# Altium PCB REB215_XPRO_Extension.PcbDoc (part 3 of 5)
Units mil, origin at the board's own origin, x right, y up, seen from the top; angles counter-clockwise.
Board outline 4055.74 x 2606 mil, 6 copper layers (Top Layer LF-signals, Signal Layer 1, Internal Plane 1, Mid-1, Mid-2, Bottom Layer LF-signals), stack 58.434 mil thick; 278 components, 292 nets, 1282 pads, 1177 vias.
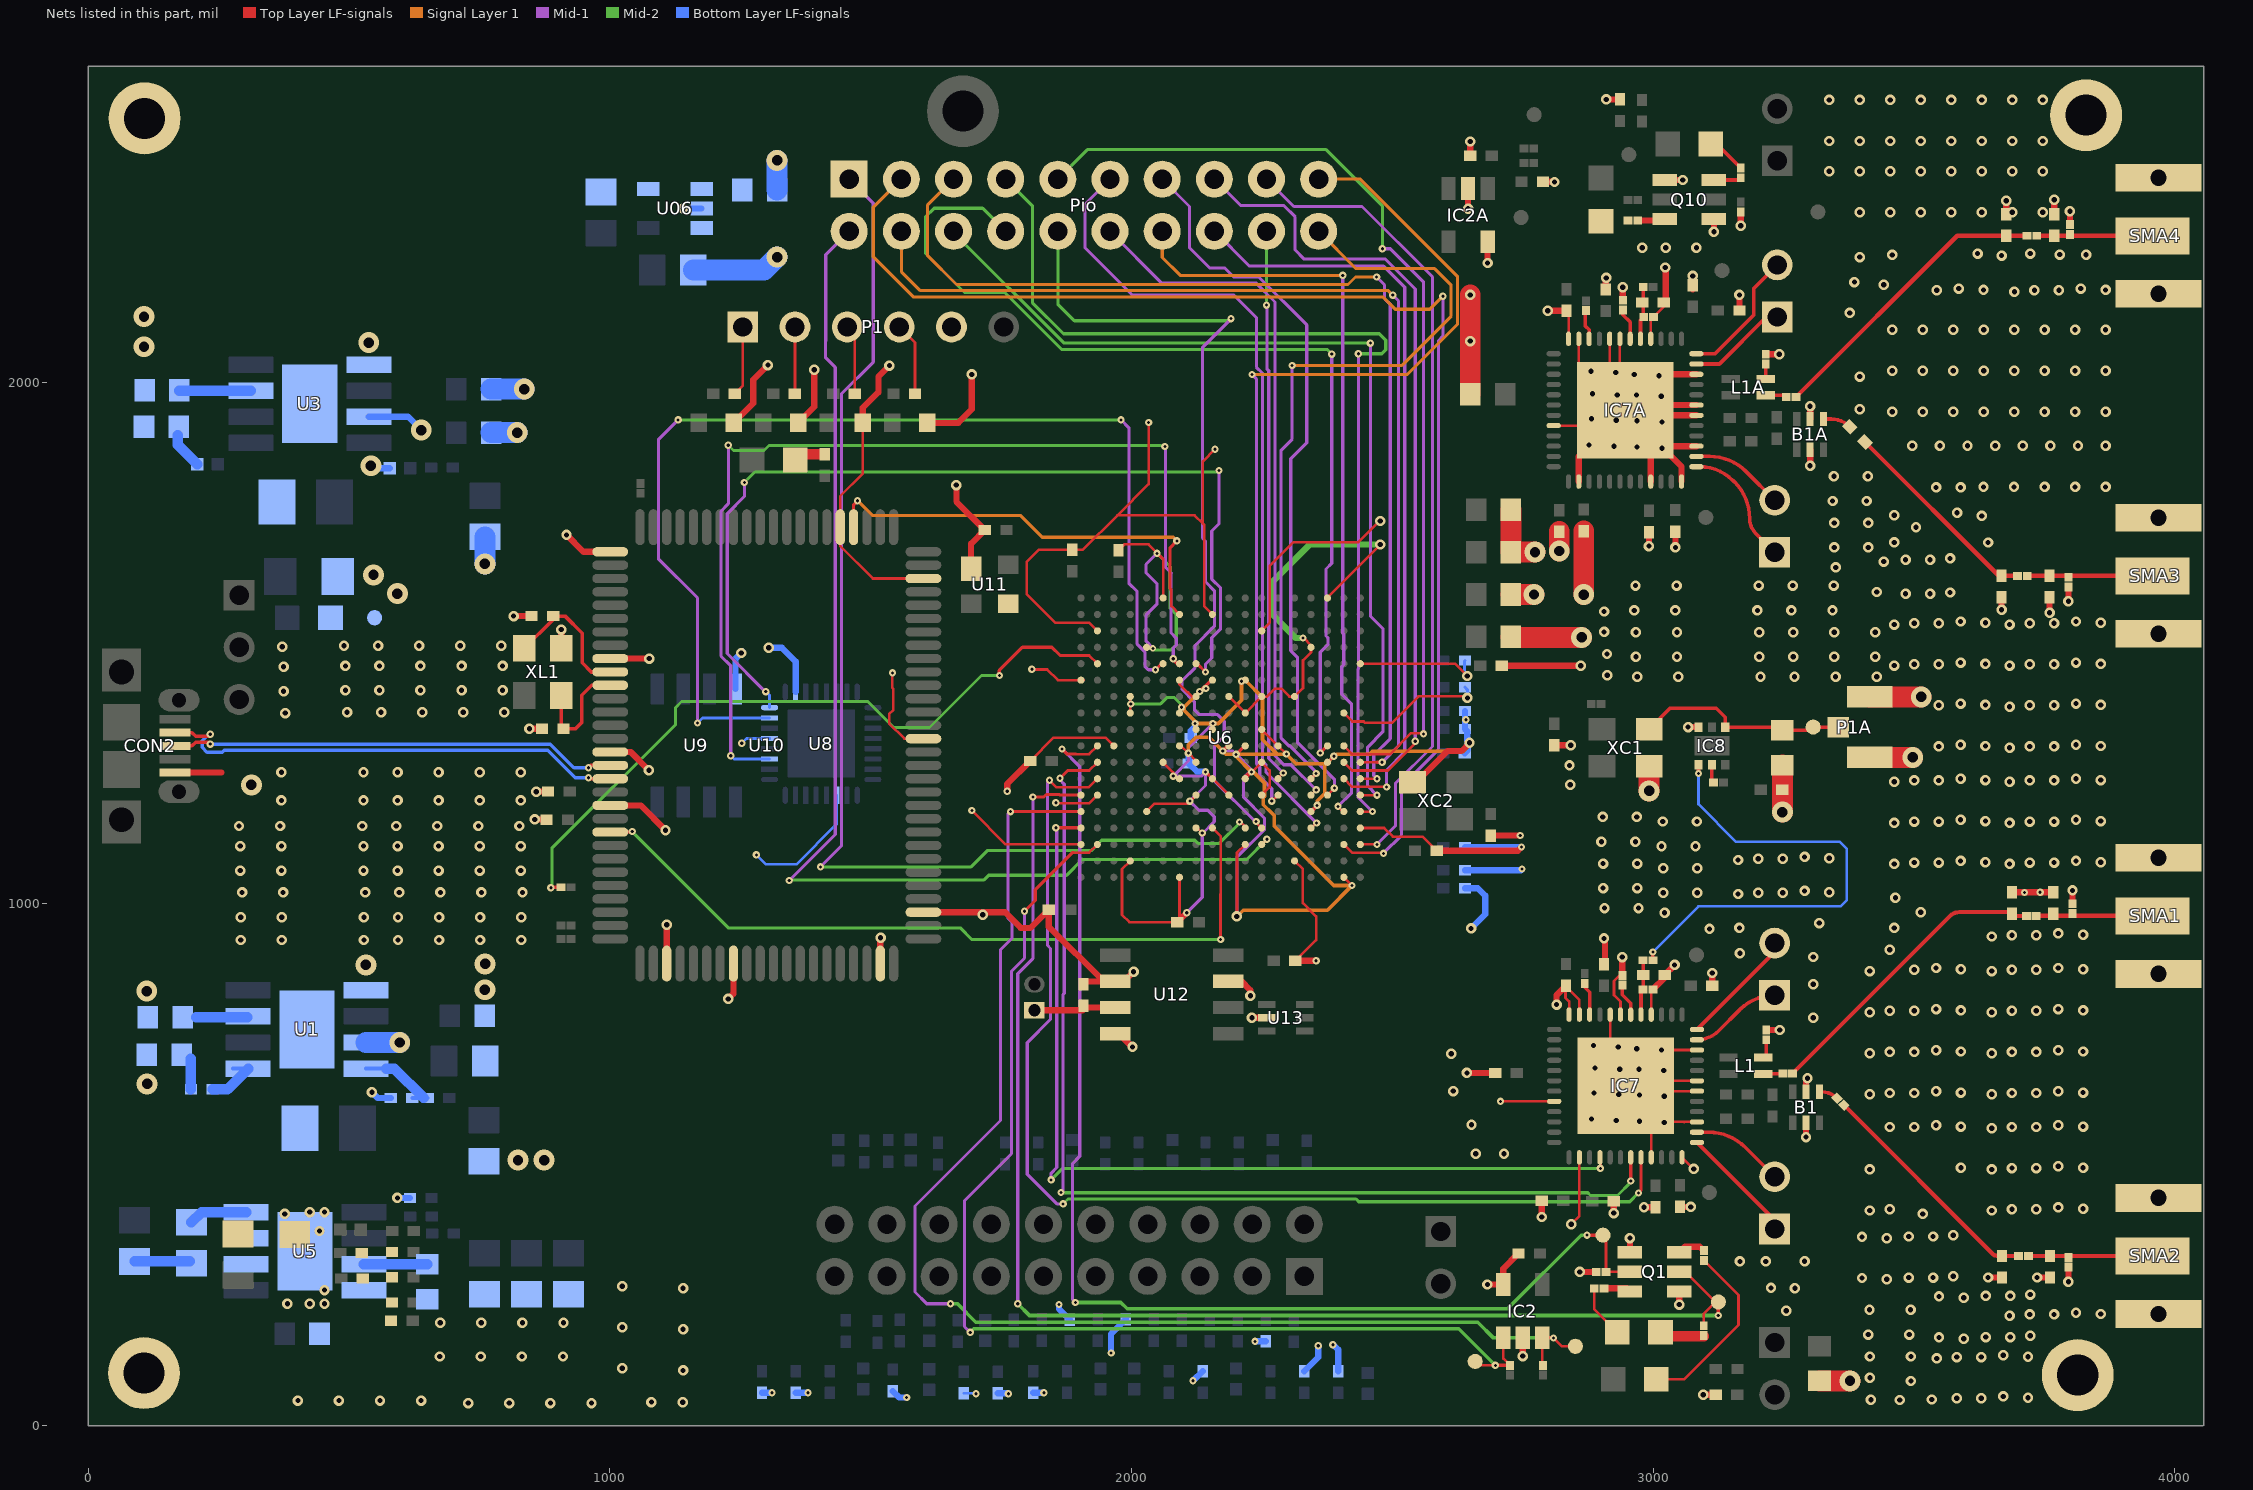
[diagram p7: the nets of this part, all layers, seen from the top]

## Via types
v1: diameter 20, hole 10, Top Layer LF-signals to Bottom Layer LF-signals, 660 vias
v2: diameter 14, hole 6, Top Layer LF-signals to Bottom Layer LF-signals, 470 vias
v3: diameter 40, hole 20, Top Layer LF-signals to Bottom Layer LF-signals, 46 vias
v4: diameter 12, hole 6, Top Layer LF-signals to Bottom Layer LF-signals, 1 vias

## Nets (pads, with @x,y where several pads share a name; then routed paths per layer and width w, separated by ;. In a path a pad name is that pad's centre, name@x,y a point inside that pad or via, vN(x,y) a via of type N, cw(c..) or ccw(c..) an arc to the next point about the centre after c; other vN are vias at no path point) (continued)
GND: B1.2 B1.5 B1A.2 B1A.5 C1.1 C01.2 C001.2 C1A.1 C002.2 C4.2 C4A.2 C5.2 C5A.2 C7.2 C7A.2 C9.2 C10.2 C10A.2 C11.1 C13.2 C13A.2 C14.2 C14A.2 C15.2 C15A.2 C16.2 C16A.2 C17.2 C17A.2 C18.2 C18A.2 C19.2 C19A.2 C20.2 C20A.2 C21.2 C21A.2 C22.2 C22A.2 C23.2 C24.2 C024A.2 C24A.2 C26.2 C27.2 C28.2 C29.2 C30.2 C31.2 C32.2 C33.2 C34.2 C35.2 C43.2 C44.2 C45.2 C46.2 C47.2 C48.2 C49.2 C50.2 C51.2 C52.2 C53.2 C54.2 C55.2 C56.2 C57.2 C58.2 C59.2 C60.2 C61.2 C62.2 C63.2 C64.2 C65.2 C66.2 C67.2 C68.2 C69.2 C70.2 C71.2 C72.2 C73.2 C74.2 C75.2 C76.2 C77.2 C78.2 C79.2 C80.2 C81.2 C82.2 C110.1 C230.2 CON2.5 D001.1 DA.1 DB.1 DC.1 DD.1 IC2.2 IC2.5 IC2A.2 IC2A.5 IC7.3 IC7.6 IC7.7 IC7.10@3084.06,719.91 IC7.16@2996.46,787.82 IC7.19 IC7.20 IC7.23 IC7.24 IC7.32 IC7.38 IC7.45 IC7.48 IC7.49 IC7A.3 IC7A.6 IC7A.7 IC7A.10@3083.06,2015.37 IC7A.16@2995.46,2083.28 IC7A.19 IC7A.20 IC7A.23 IC7A.24 IC7A.32 IC7A.38 IC7A.45 IC7A.48 IC7A.49 IC8.3 P1.5 P1A.2 P1A.3 pad.0 pad.1 pad.3 pad.4 Q1.1 Q1.4 Q10.1 Q10.4 R5.2 R5A.2 R7.2 R7A.2 R10.1 R10A.1 R11.1 R11A.1 R13.1 R13A.1 R16.1 R19.1 R25.2 R032.2 R46.2 R47.2 R48.2 R49.2 R50.2 R51.2 R53.1 R54.1 R55.1 R56.1 R57.1 R58.1 SMA1.2 SMA1.2.1 SMA2.2 SMA2.2.1 SMA3.2 SMA3.2.1 SMA4.2 SMA4.2.1 TP9.1 U1.1 U1.3 U3.1 U3.3 U5.9 U06.2 U6.A2 U6.A12 U6.B5 U6.B15 U6.C8 U6.C18 U6.D1 U6.D11 U6.E4 U6.E14 U6.F7 U6.F9 U6.F11 U6.F17 U6.G8 U6.G10 U6.G12 U6.H3 U6.H7 U6.H11 U6.H13 U6.J6 U6.J8 U6.J9 U6.J12 U6.J16 U6.K7 U6.K10 U6.K11 U6.L2 U6.L8 U6.L12 U6.L15 U6.M5 U6.M7 U6.M9 U6.M11 U6.M15 U6.N8 U6.N10 U6.N12 U6.N18 U6.P1 U6.R4 U6.R14 U6.T7 U6.T17 U6.U10 U6.V3 U6.V13 U8.11 U8.21 U8.26 U9.4 U10.1 U10.9 U10.16 U10.20 U10.33 U10.38 U10.49 U10.53 U10.66 U10.78 U10.85 U11.1 U12.2 U12.4 U12.7 U13.2 XC1.2 XC2.2 XL1.2 | length 19395.7
  Top Layer LF-signals w5: DB.1@1484.99,1922.18 1484.99,1825.03 1441.75,1781.78 U10.85@1441.75,1722.31 1441.75,1686.25 1504.12,1623.88 U10.78@1601.2,1623.88 ; v2(1541.76,1443) 1541.76,1414.15 1543.41,1412.51 1543.41,1371.74 1535.59,1363.93 1535.59,1345.78 1564.58,1316.8 U10.66@1601.2,1316.8 ; U11.1@1689,1646.1 1689,1686.79 1692.57,1690.36 ; v2(1694,1179) 1758.95,1114.05 U6.C18@1903.2,1114.05 ; C73.2@1806,1274 1850.77,1318.77 1950.45,1318.77 U6.J16@1966.19,1303.02 ; v2(1809,1450) 1808.51,1449.49 1838.31,1449.49 1858.79,1429.01 U6.N18@1903.2,1429.01 U6.N18@1908.65,1429.01 ; v2(1855,1194) 1856.21,1192.79 1918.95,1192.79 U6.F17@1934.7,1208.54 ; U6.T17@1934.7,1523.5 1918.95,1539.24 1853.61,1539.24 1799,1593.85 1799,1655.68 1822.32,1679 C74.2@1886.73,1679 1906.91,1679 1972.91,1745 ; U12.2@1946.55,851.45 U12.2@1968.83,851.45 ; C75.2@1975,1687.12 C75.2@1975,1678 1986.41,1689.41 2033.01,1689.41 2060.68,1661.73 2060.68,1660.32 ; U6.B15@1997.69,1082.55 1981.94,1066.8 1981.94,978.94 1995.88,965 C71.2@2088,965 ; U6.L15@1997.69,1366.02 U6.M15@1997.69,1397.51 ; U6.R14@2028.59,1492.59 U6.R14@2029.19,1492 v4@2039,1492 ; U6.E14@2029.19,1177.04 2044.48,1192.34 2107.34,1192.34 v2(2112,1197) 2113,1197 2123.67,1207.67 U6.F11@2123.67,1208.54 ; v2(2032.98,1923) 2032.98,1805.08 1972.91,1745 ; v2@2046.84,1674.16 v2(2049,1672) 2060.68,1660.32 ; U6.H13@2060.68,1271.53 2080,1252.21 v2(2080,1245) ; U6.V13@2060.68,1586.49 2060.68,1660.32 ; C71.2@2092.18,969.18 U6.A12@2092.18,1051.06 ; U6.G12@2092.18,1240.03 U6.G12@2092.18,1242.64 ; U6.J12@2092.18,1303.02 2094.98,1303.02 v2(2109,1289) 2123.67,1274.33 U6.H11@2123.67,1271.53 ; U6.L12@2092.18,1366.02 2093.41,1367.24 v2@2093.41,1380.86 ; U6.N12@2092.18,1429.01 2092.18,1421.04 2107.62,1405.6 2108.41,1405.6 2116.49,1397.51 ; U6.D11@2123.67,1145.54 2126.12,1145.54 v2(2135.66,1136) v2@2139,1132.66 ; 2147,1248.2 U6.G10@2155.17,1240.03 U6.F9@2186.67,1208.54 ; U6.U10@2155.17,1554.99 2139.42,1570.74 2139.42,1726.58 2136.84,1729.16 ; v2(2160,1871.67) 2136.84,1848.51 2136.84,1729.16 ; U6.M9@2186.67,1397.51 U6.L8@2218.16,1366.02 U6.M7@2249.66,1397.51 2259.52,1397.51 2274.82,1412.81 2287.49,1412.81 2302.79,1397.51 U6.M5@2312.65,1397.51 2328.85,1413.71 2328.85,1466.84 2344.15,1482.14 U6.R4@2344.15,1492 2340.79,1492 2344.63,1495.84 2330.68,1509.79 v2(2328.72,1509.79) ; v1(2202,976) 2202.41,976.41 2202.41,1098.3 U6.C8@2218.16,1114.05 ; v2@2210,1422 2217.01,1429.01 U6.N8@2218.16,1429.01 ; v2(2230,1253) 2226,1253 2213.03,1240.03 U6.G8@2218.16,1240.03 U6.H7@2249.66,1271.53 2264.95,1256.23 2264.95,1223.83 U6.F7@2249.66,1208.54 ; U6.K7@2249.66,1334.52 U6.J6@2281.15,1303.02 v2(2296.9,1287.28) ; U6.T7@2249.66,1523.5 2265.41,1539.24 2265.41,1648.5 2309.91,1693 2434.08,1693 2475.15,1734.07 v1(2476.91,1734.07) v1@2476.77,1733.94 ; U6.B5@2312.65,1082.55 2328.4,1066.8 2328.4,1001.6 2353.89,976.11 2353.89,930.89 2314.33,891.33 C68.2@2314,891 ; U6.H3@2375.64,1271.53 2388,1283.89 v2(2388,1283) ; U6.V3@2375.64,1586.49 2375.64,1587.64 v1(2477,1689) ; U6.A2@2407.14,1051.06 v2(2422.89,1035.31) ; U6.L2@2407.14,1366.02 2423.34,1349.82 2444.97,1349.82 2447.78,1347 2499,1347 2550,1398 v1@2641,1398 ; U6.D1@2438.63,1145.54 2484.36,1145.54 2500.9,1129 2558.09,1129 C76.2@2585,1102.1 ; U6.P1@2438.63,1460.5 2620.35,1460.5 v1(2643.91,1436.95) ; v2(2707.48,621.48) IC7.32@2810.43,621.48 ; IC7A.32@2809.43,1916.95 IC7A.49@2916.72,1916.95 ; IC7A.24@2837.98,2083.28 C24A.2@2837.98,2133.01 ; IC7.24@2838.98,787.82 2838.98,813.02 2832,820 2832,842.38 2858.66,815.72 IC7.23@2858.66,787.82 ; v1(2843,386) 2858.66,401.66 IC7.38@2858.66,514.2 ; IC7A.49@2857.66,2035.06 IC7A.23@2857.66,2083.28 ; IC7A.49@2916.72,1976 IC7A.20@2916.72,2083.28 ; IC7.49@2917.72,680.54 IC7.20@2917.72,787.82 ; R7.2@2935.77,863.07 2925.05,852.35 2925.05,825.01 2937.4,812.66 IC7.19@2937.4,787.82 ; IC7A.49@2936.4,1956.32 IC7A.19@2936.4,2083.28 ; IC7.49@2947.24,651.01 IC7.49@2957.09,641.17 ; IC7.49@2957.09,660.85 IC7.7@3084.06,660.85 ; IC7A.16@2995.46,2083.28 2995.46,2119.76 R13A.1@3000.7,2125 C10A.2@3020.34,2144.64 ; IC7.45@2996.46,514.2 2996.46,601.8 IC7.49@2957.09,641.17 ; IC7.16@2996.46,787.82 R13.1@2996.46,832.95 ; IC7.49@3016.14,582.11 3060.11,582.11 ; v1(3016.14,719.91) IC7.10@3084.06,719.91 ; IC7.48@3055.51,514.2 v1(3077.71,492) ; 3060,582 3060.11,582.11 ; IC7.3@3084.06,582.11 3060.11,582.11 ; IC7.6@3084.06,641.17 IC7.49@2957.09,641.17 ; 1972.91,1745 2121,1745 2136.84,1729.16
  Top Layer LF-signals w6: v2@2707,621 v2(2707.48,621.48)
  Top Layer LF-signals w7: U6.M11@2123.67,1397.51 2123.67,1399.85 v2(2131,1407.17) 2152.84,1429.01 U6.N10@2155.17,1429.01 ; v2(2142,1253.2) 2147,1248.2 ; U6.G10@2153.68,1240.03 U6.G10@2155.17,1240.03 ; v2(2175,1293) 2185.02,1303.02 U6.J9@2186.67,1303.02 ; v2(2200.73,1286.81) 2216.95,1303.02 U6.J8@2218.16,1303.02 ; U6.E4@2344.15,1177.04 v2(2356,1188.89)
  Top Layer LF-signals w12: CON2.5@166.24,1251.82 255.61,1251.82 ; v1(815.57,1551.81) C002.2@850,1551.81 ; v1(845.84,1336) C01.2@870,1336 ; v1@857.74,1162 v1(856,1162) 856.37,1161.63 C69.2@878.66,1161.63 ; v1(859,1215) 859.4,1215.4 C67.2@881.66,1215.4 ; XL1.2@906.87,1489.99 906.87,1525.87 v1(907,1526) v1@907,1526.65 ; v1(917,1707.47) 949.41,1675.06 U10.1@1000.8,1675.06 ; U10.20@1000.8,1188.84 1059.16,1188.84 v1(1106.78,1141.22) ; U10.16@1000.8,1291.21 1040.03,1291.21 v1(1075,1256.23) ; U10.9@1000.8,1470.34 v1(1075.66,1470.34) ; U10.33@1109.07,885.69 v1(1109.07,959.93) ; v1(1227,818) 1237.02,828.02 U10.38@1237.02,885.69 ; DD.1@1237.6,1922.18 1275,1959.58 1275,2005 v1(1303,2033) ; DC.1@1361.3,1922.18 1392,1952.88 v1(1392,2024) ; DB.1@1484.99,1922.18 1484.99,1950.99 1515,1981 1515,2011 v1(1536,2032) ; U10.49@1518.52,885.69 1518.52,934.52 v1(1519,935) v1@1519,935.56 ; U10.53@1601.2,984.12 v1@1709.77,984.12 ; DA.1@1608.69,1922.18 1667.82,1922.18 1694,1948.36 v1(1694,2015) ; v1(1664,1803) 1664.47,1802.53 1664.47,1771.32 C65.2@1719,1716.79 1692.57,1690.36 U11.1@1692.57,1642.53 ; v1(1714.81,979.08) v1@1709.77,984.12 ; v2(1762,1216) 1762,1230 C73.2@1806,1274 ; R032.2@1908,846.34 1913.11,851.45 1946.55,851.45 1841.66,956.34 C72.2@1841.66,989 1806.66,954 1788,954 1757.88,984.12 v1@1709.77,984.12 ; U12.4@1968.83,751.45 1975.55,751.45 2001,726 v1(2002,726) ; U12.2@1968.83,851.45 1985.45,851.45 v1(2004,870) ; C71.2@2088,965 C71.2@2088,965 v2(2106.06,983) ; U12.7@2185.36,851.45 2211.45,851.45 2228,834.91 v1(2228,824) ; v1(2231,782) 2231.23,781.77 U13.2@2259.53,781.77 ; C68.2@2314.33,891.33 2353.67,891.33 v2(2354,891) v2@2353.33,891 ; XC2.2@2538.72,1233.43 2546.02,1233.43 2605.69,1293.1 2632.83,1293.1 v1@2648,1308.26 ; C76.2@2585,1102.1 2740.79,1102.1 v2(2747.85,1109.15) ; v1(2643,676) C15.2@2697.57,676 ; v1(2645.26,2332.74) IC2A.2@2645.26,2371.52 ; C14A.2@2649.37,2434.37 v1(2649.37,2461.54) ; v1(2682.46,270.46) IC2.5@2712.73,270.46 2712.73,300.73 C1.1@2742,330 ; v1(2682.66,2228.66) IC2A.5@2682.66,2269.16 ; C70.2@2689,1131 v2(2745.37,1131) ; C66.2@2709.84,1456.5 v1(2861.18,1456.5) ; v1(2750.13,133.13) IC2.2@2750.13,168.09 ; v1(2786.66,399.82) C18.2@2786.66,431 ; C1A.1@2789,2384.28 2810.72,2384.28 v1(2811,2384) ; v1@2798.48,2137.48 v1(2798,2137) C24A.2@2834,2136.99 ; C9.2@2810.43,1304 v1(2842.18,1304) ; v1(2815,807) 2815,825.38 2832,842.38 C24.2@2833,843.38 ; IC7A.38@2857.66,1809.66 IC7A.49@2857.66,1857.89 ; v1(2859.41,294.59) R5.2@2891.02,294.59 ; C13.2@2905.9,884.68 2907.91,886.68 2907.91,931.9 v1(2905.9,933.9) ; C15A.2@2909,2178 2909,2199 v1(2910,2200) ; v1(2909.98,2542.28) C110.1@2936.35,2542.28 ; v1(2924.61,407.4) C17.2@2924.61,430 ; R7.2@2941,863.07 v1(2941,898) ; R7A.2@2942,2157.35 v1(2942,2182) ; IC7A.49@2946.24,1946.47 IC7A.49@2956.09,1936.63 ; Q1.4@2955.49,331.99 v1(2955.49,359.51) ; IC7A.49@2956.09,1956.32 IC7A.7@3083.06,1956.32 ; v1(2982.57,418.66) C16.2@3004.49,418.66 ; v1(2992,1686) C16A.2@2992,1712.66 ; IC7A.45@2995.46,1809.66 IC7A.49@2995.46,1897.26 ; R13.1@2999.51,836 3022.15,858.64 C10.2@3022.15,863.95 v1(3041.2,883) v1@3042,883 ; IC7A.49@3015.14,2015.37 IC7A.10@3083.06,2015.37 ; C10A.2@3020.34,2153 3024.11,2156.77 3024.11,2219.11 v1(3023.21,2220) ; Q10.1@3022.07,2387.77 v1(3056.77,2387.77) ; v1(3042.7,1683.39) C19A.2@3042.7,1713.76 ; v1(3049.98,232.02) Q1.1@3049.98,257.19 ; C19.2@3051.58,419.24 v1(3072.24,419.24) ; IC7A.48@3054.51,1809.66 3054.51,1838.21 IC7A.49@3015.14,1877.58 ; v1(3067,1339.02) IC8.3@3087.03,1339.02 ; C17A.2@3076,2178.32 v1(3076,2204) ; IC7A.3@3083.06,1877.58 IC7A.49@3015.14,1877.58 ; IC7A.6@3083.06,1936.63 IC7A.49@2956.09,1936.63 ; v1(3096,59) C11.1@3120.09,59 ; C20.2@3113.34,843.34 v1(3113.34,867.66) ; v1(3116.56,2288.56) Q10.4@3116.56,2312.97 ; C20A.2@3165.49,2137.65 v1(3165.49,2167.46) ; v1(3168,2300) R5A.2@3168,2326.62 ; C5A.2@3216,2053.75 v1(3241.75,2053.75) ; C5.2@3217,758.35 v1(3242.65,758.35) ; v1(3293.11,553.11) B1.5@3293.11,580.61 ; B1.2@3293.11,639.66 3293.11,663.11 v1(3296,666) v1@3295.54,666.46 ; v1(3301,1840) B1A.5@3301,1870.47 ; B1A.2@3301,1929.53 v1(3301,1954) v1@3301,1952.72 ; v1(3642.17,283.83) C21.2@3668.65,283.83 ; v1(3668,1564.1) C21A.2@3668,1587.61 ; C22A.2@3677,2322.17 v1(3677,2348) ; C22.2@3688,1022.34 C7.2@3767,1022.34 ; v1(3736.17,283.83) C4.2@3761,283.83 ; v1(3760,1558) C4A.2@3760,1587.61 ; C7A.2@3769,2322.34 v1(3769,2350) ; v1(3796.17,275.83) R10.1@3796.17,303.65 ; v1(3796.17,1580.17) R10A.1@3796.17,1607.65 ; R11A.1@3799,2302.35 v1(3799,2328) ; R11.1@3804,1000.35 v1(3804,1026) ; IC7A.49@2956.09,1936.63 IC7A.49@2995.46,1897.26 ; IC7A.49@2995.46,1897.26 IC7A.49@3015.14,1877.58
  Top Layer LF-signals w40: C230.2@2649.54,1977 v1(2649.54,2079.05) v1(2649.54,2167.54) ; C80.2@2727.47,1512 2728.47,1511 v3(2863,1511) ; C82.2@2727.47,1593.21 v3(2771.71,1593.21) ; C79.2@2727.47,1755.63 C81.2@2727.47,1674.42 v3(2773.58,1674.42) ; v3(2820,1676.52) C18A.2@2820,1713.66 ; v3(2867,1592.92) C13A.2@2867,1714.66 ; v3(2992.43,1216.57) XC1.2@2992.43,1264.13 ; v3(3247.84,1176.16) C024A.2@3247.84,1266.1 ; C23.2@3319,85.54 v3(3377.47,85.54) ; P1A.3@3415.16,1280.87 v3(3497.71,1280.87) ; P1A.2@3415.16,1397.01 v3(3513.92,1397.01)
  Mid-1 w6: v2(1998.56,1383.44) v2@1998.56,1384.57 ; v4(2041,1490) 2041,1490.51 2028.09,1503.41 2028.09,1554.1 2049.18,1575.18 2049.18,1613.33 2027.87,1634.64 2027.87,1650.87 v2(2049,1672) ; v2(2096,1377) 2096,1375.49 2125.49,1346 v2(2156,1346) 2109,1299 v2(2109,1289) 2109,1274 v2(2080,1245) 2133.8,1245 v2(2142,1253.2) 2142,1227 v2(2112,1197) 2129.44,1179.56 2146.44,1179.56 2158.72,1167.28 2158.72,1158.12 2159.01,1157.83 2137.18,1136 v2(2135.66,1136) 2135.66,1012.6 v2(2106.06,983) ; v2(2175,1293) 2194.55,1293 v2(2200.73,1286.81) 2230,1257.55 2214.92,1242.46 2214.92,1204.58 2254.91,1164.59 2254.91,1142.1 2202,1089.19 v1(2202,976)
  Mid-2 w6: v2(1998.56,1383.44) 2055.94,1383.44 2068.41,1395.91 2081.59,1395.91 2096,1381.49 v2(2096,1377) ; v4(2041,1490) 2043.91,1487.1 2076.59,1487.1 2085.91,1496.41 2085.91,1554.74 2074.09,1566.55 2074.09,1646.91 v2(2049,1672)
  Mid-2 w12: v2(2328.72,1509.79) 2315.18,1509.79 2269,1555.97 2269,1616.25 2341.76,1689 v1(2477,1689)
  Signal Layer 1 w6: v2(1998.56,1383.44) v2@1998.56,1386.74
  Signal Layer 1 w7: v2(2109,1289) 2109,1305 2123.22,1319.22 2148.78,1319.22 v2(2175,1293) 2181.19,1286.81 v2(2200.73,1286.81) ; v2(2131,1407.17) 2100.83,1377 2100.83,1371.37 2126.2,1346 v2(2156,1346) 2166.65,1346 2211,1390.35 v2(2211,1427) 2220.17,1427 2251.28,1395.89 2251.28,1314.81 2278.82,1287.28 v2(2296.9,1287.28) ; v1(2202,976) 2214.04,988.04 2375.62,988.04 v2(2422.89,1035.31) 2387.79,1035.31 2273.86,1149.23 2273.86,1169.54 2262.81,1180.6 2262.21,1180.6 2252.59,1190.21 2252.59,1203.8 2254.91,1206.11 2254.91,1231.92 2233.83,1253 v2(2230,1253) 2200.73,1282.27 v2(2200.73,1286.81) ; v2(2356,1188.89) 2356,1197.19 2370.62,1211.81 2370.62,1265.62 ; v1(2648,1309) 2632,1293 2462.96,1293 2457.23,1287.28 2392.28,1287.28 v2(2388,1283) 2374,1269 2315.18,1269 v2(2296.9,1287.28) ; v2(2200.73,1286.81) 2296.44,1286.81 v2(2296.9,1287.28)
  Bottom Layer LF-signals w5: v2(1253,1308) 1262.16,1317.16 U8.21@1306.35,1317.16 ; v2(1281,1094) 1299.09,1075.91 1357.91,1075.91 1434.9,1152.9 U8.11@1434.9,1208.31 ; R46.2@1678.61,62.03 1700.98,62.03 v2(1702,61) v2@1702.32,61.32
  Bottom Layer LF-signals w6: C55.2@2639.34,1415.42 2644,1410.76 v1(2644,1395) v1@2642,1395 ; C56.2@2639.34,1466.6 2638.35,1465.61 2638.35,1442.5 v1(2643.91,1436.95) v1@2643.91,1439.97
  Bottom Layer LF-signals w12: U3.3@538.06,1933.78 613.22,1933.78 v3(638.54,1908.47) v3@642,1908.47 ; v3(542,1840) 546.59,1835.41 R19.1@578.12,1835.41 ; v1(544,639) 555,628.01 R16.1@580.01,628.01 ; v1@591.22,438 v1(592.83,436.39) R25.2@617,436.39 ; v1(1140.16,2333.16) U06.2@1175.87,2333.16 ; U9.4@1241,1412 1241,1470 v1(1252,1481) 1254.51,1483.51 v1@1253.03,1484.98 ; R58.1@1291.68,63.03 v2(1311,63.03) ; v1(1304.49,1491) 1330,1491 1356.41,1464.59 1356.41,1406.61 U8.26@1356.1,1406.31 ; R53.1@1356.67,63.03 v2(1380,63.03) ; R51.2@1542.43,66 1554.43,54 v2(1569,54) ; R49.2@1743.59,62.03 1762.98,62.03 v2(1764,61) v2@1764,61.67 ; R50.2@1811.56,63.03 v2(1832,63.03) ; v2(1861,232) 1861,223.59 R54.1@1881.8,202.79 ; v2(1961,139) 1961,175.64 R55.1@1989.13,203.77 ; v2@2110,1288 C53.2@2110,1269 2125.8,1253.2 v2(2142,1253.2) ; C54.2@2113.57,1318 2113.57,1331.83 v2@2122,1340.26 ; v2(2118,85.87) R48.2@2136.49,104.36 ; v2(2236.85,161.45) R57.1@2257.44,161.45 ; R56.1@2331.44,104.36 2358,130.92 v2(2358,153) ; v2(2386,155) 2387.15,155 2396.43,145.72 R47.2@2396.43,104.36 ; C61.2@2639,1289 2643.91,1293.91 2643.91,1304.91 v1(2648,1309) v1@2649.5,1310.5 ; C57.2@2639.34,1030 2664,1030 2678,1016 2678,980 v1(2651,953) ; C60.2@2639.34,1064.74 2746.74,1064.74 v2(2748.8,1066.8) ; C62.2@2639.34,1109.15 v2(2747.85,1109.15) ; v2@2639.34,1351.34 C59.2@2639.34,1335.24 2643.91,1330.67 v1@2643.91,1313.1 ; C58.2@2639.34,1369.87 2639.34,1354.25 2640.59,1353 v2(2641,1353)
  Bottom Layer LF-signals w40: U1.3@532.54,734.4 v3(597.4,734.4) ; v3(760.5,1652) C35.2@760.5,1703.63 ; C34.2@772.47,1903.47 v3(822.47,1903.47) ; C31.2@772.47,1986.8 v3(836.01,1986.8) ; C48.2@1160.12,2215.05 1295.72,2215.05 v3(1320.67,2240) ; C47.2@1320.67,2368.6 v3(1320.67,2425.33)
  other v1: 728.65,43.16 807.39,43.16 886.13,43.16 964.87,43.16 1079.67,45 1140.02,44.61 402,48 480.74,48 559.48,48 638.22,48 3473,49 3417.63,49.6 3534,50.05 3582.23,52.56 3629.14,52.56 3718.66,53.35 3671.14,55.9 3494.31,85.46 3415.57,91.84 1140.47,105.74 1024,109.74 3543.77,128.74 3582.23,131.3 3629.14,131.3 3718.66,132.09 674,132.36 752.74,132.36 831.48,132.36 910.22,132.36 3415.57,132.36 3494.31,132.36 3671.14,134.64 3595.64,166.4 3548.11,168.95 3637.64,169.74 3684.54,169.74 3723,172.3 3412.23,174.36 3490.97,174.36 1140.47,184.48 1024,188.48 675,197 753.74,197 832.48,197 911.22,197 3683.38,210.6 3721.84,213.16 3768.74,213.16 3858.27,213.95 3810.74,216.5 3255.3,220.32 3414.78,221.89 3493.52,221.89 381.87,233.54 424.68,233.54 453.06,233.54 3595.64,245.14 3548.11,247.69 3637.64,248.48 3684.54,248.48 3723,251.04 453.06,259.69 3271.94,263.1 1140.47,263.22 3226.02,263.97 1024,267.22 3447.91,280.36 3400.39,282.91 3489.91,283.7 3536.82,283.7 3575.27,286.26 3166.42,314.63 3215.94,314.63 3290.32,314.96 3447.91,359.1 3400.39,361.65 3489.91,362.44 3536.82,362.44 3575.27,365 443.47,373 377,405.67 3516.84,405.67 424.68,409.18 453.06,409.18 3415.16,412.3 3649.3,412.3 3453.62,414.86 3687.76,414.86 3734.66,414.86 3824.19,415.65 3776.66,418.2 3415.16,491.04 3649.3,491.04 3687.76,493.6 3734.66,493.6 3590.05,494.39 3824.19,494.39 3776.66,496.94 2660,521.31 2714.15,521.31 3649.3,569.78 3453.62,572.34 3500.53,572.34 3590.05,573.13 3687.76,572.34 3734.66,572.34 3824.19,573.13 3542.53,575.68 3776.66,575.68 2651.85,576.6 3021.42,581 2973.9,583.55 2929.46,584.91 2881.94,587.46 3021.42,631.32 2973.9,633.87 2934.13,634.83 3415.16,635.02 3649.3,635.02 2886.6,637.38 3453.62,637.57 3500.53,637.57 3687.76,637.57 3734.66,637.57 3590.05,638.36 3824.19,638.36 2616.99,641.17 3542.53,640.91 3776.66,640.91 3020.34,680.54 2936,683.09 2972.81,683.09 2888.47,685.64 2613.15,713 3415.16,713.76 3649.3,713.76 3453.62,716.31 3500.53,716.31 3590.05,717.1 3687.76,716.31 3734.66,716.31 3824.19,717.1 3542.53,719.65 3776.66,719.65 2968.62,722.46 2933.03,726 2885.5,728.55 3307.09,781.77 3415.16,792.5 3649.3,792.5 3453.62,795.06 3500.53,795.06 3687.76,795.06 3734.66,795.06 3590.05,795.84 3824.19,795.84 3542.53,798.39 3776.66,798.39 3306.9,846 3415.16,871.24 3649.3,871.24 3500.53,873.8 3687.76,873.8 3734.66,873.8 3590.05,874.58 3824.19,874.58 3542.53,877.13 3776.66,877.13 3307.09,898.24 3166.42,905.51 3453.62,912.13 292.44,930.89 371.18,930.89 528.66,930.89 593.9,930.89 672.64,930.89 751.38,930.89 830.12,930.89 3649.3,937.56 3687.76,940.12 3734.66,940.12 3824.19,940.91 3776.66,943.46 3108.1,952.1 3165.49,954 3462.15,954 3318.7,963.32 292.44,974.47 371.18,974.47 528.66,974.47 593.9,974.47 672.64,974.47 751.38,974.47 830.12,974.47 3021.99,983.13 3513.14,984.25 2906.76,992 2972,992 3464.57,1012 3162.96,1019.02 294.99,1022 373.73,1022 531.21,1022 596.45,1022 675.19,1022 753.93,1022 832.67,1022 3019.43,1021.58 3084.66,1021.58 3201.41,1021.58 3248.32,1021.58 3337.84,1022.37 3290.32,1024.92 2904.21,1030.46 2969.44,1030.46 291.65,1064 370.39,1064 527.87,1064 593.11,1064 671.85,1064 750.59,1064 829.33,1064 3019.43,1068.49 3084.66,1068.49 3462.15,1076.65 3683.38,1076.65 2904.21,1077.36 2969.44,1077.36 3500.61,1079.21 3547.51,1079.21 3637.04,1080 3721.84,1079.21 3768.74,1079.21 3858.27,1080 3589.51,1082.55 3810.74,1082.55 3162.96,1084.26 3201.41,1086.81 3248.32,1086.81 3337.84,1087.6 3290.32,1090.15 291.65,1110.91 370.39,1110.91 527.87,1110.91 593.11,1110.91 671.85,1110.91 750.59,1110.91 829.33,1110.91 3016.09,1110.49 3081.32,1110.49 2900.87,1119.36 2966.1,1119.36 289.1,1149.36 367.84,1149.36 525.32,1149.36 590.55,1149.36 669.29,1149.36 748.03,1149.36 826.77,1149.36 3462.15,1155.39 3683.38,1155.39 3018.64,1158.01 3083.88,1158.01 3500.61,1157.95 3547.51,1157.95 3721.84,1157.95 3768.74,1157.95 3637.04,1158.74 3858.27,1158.74 3589.51,1161.29 3810.74,1161.29 2903.42,1166.89 2968.65,1166.89 370.39,1198.53 527.87,1198.53 593.11,1198.53 671.85,1198.53 750.59,1198.53 829.33,1198.53 2841,1228.3 3462.15,1234.13 3683.38,1234.13 3500.61,1236.69 3547.51,1236.69 3721.84,1236.69 3768.74,1236.69 3637.04,1237.48 3858.27,1237.48 3589.51,1240.03 3810.74,1240.03 370.39,1252.56 527.87,1252.56 593.11,1252.56 671.85,1252.56 750.59,1252.56 829.33,1252.56 2839.66,1265.62 3683.38,1299.37 3547.51,1301.93 3721.84,1301.93 3768.74,1301.93 3637.04,1302.72 3858.27,1302.72 3589.51,1305.27 3810.74,1305.27 378,1365.85 496.38,1367.45 561.61,1367.45 640.35,1367.45 719.09,1367.45 797.83,1367.45 3683.38,1378.11 3547.51,1380.67 3721.84,1380.67 3768.74,1380.67 3637.04,1381.46 3858.27,1381.46 3589.51,1384.01 3810.74,1384.01 374.66,1407.85 493.04,1409.45 558.28,1409.45 637.02,1409.45 715.76,1409.45 794.5,1409.45 2969.61,1435.41 3048.35,1435.41 3205.83,1435.41 3271.06,1435.41 3349.8,1435.41 3428.54,1435.41 2912,1438.53 374.66,1454.75 493.04,1456.35 558.28,1456.35 637.02,1456.35 715.76,1456.35 794.5,1456.35 3462.15,1456.85 3683.38,1456.85 3500.61,1459.41 3547.51,1459.41 3721.84,1459.41 3768.74,1459.41 3637.04,1460.2 3858.27,1460.2 3589.51,1462.75 3810.74,1462.75 2967.05,1473.86 3045.79,1473.86 3203.27,1473.86 3268.5,1473.86 3347.24,1473.86 3425.98,1473.86 2911.57,1479.09 372.1,1493.21 490.48,1494.81 555.72,1494.81 634.46,1494.81 713.2,1494.81 791.94,1494.81 2967.05,1520.77 3045.79,1520.77 3203.27,1520.77 3268.5,1520.77 3347.24,1520.77 3425.98,1520.77 2906.04,1521.52 3462.15,1535.59 3683.38,1535.59 3500.61,1538.15 3547.51,1538.15 3721.84,1538.15 3768.74,1538.15 3637.04,1538.94 3858.27,1538.94 3589.51,1541.49 3810.74,1541.49 2906.04,1560.59 2963.71,1562.77 3042.45,1562.77 3199.93,1562.77 3265.16,1562.77 3343.91,1562.77 3484.04,1594.47 3530.95,1594.47 3569.41,1597.03 3428.54,1598 2966.26,1610.29 3045,1610.29 3202.48,1610.29 3267.72,1610.29 3346.46,1610.29 3349.93,1645.1 3442.04,1656.37 3484.04,1659.71 3530.95,1659.71 3569.41,1662.27 3347.37,1683.55 3412.61,1683.55 3462.15,1693 3642.17,1692.91 3503.94,1722 3347.37,1730.46 3412.61,1730.46 3630,1743.75 3462.15,1745 3582.68,1749.98 3344.03,1772.46 3409.27,1772.46 3542.53,1798.56 3589.51,1798.56 3633.3,1799.45 3691.83,1799.45 3750.37,1799.45 3808.9,1799.45 3867.43,1799.45 3346.58,1819.98 3411.82,1819.98 3016.83,1873.55 2969.31,1876.1 2924.87,1877.45 3496.87,1878.19 3549.81,1878.19 3602.74,1878.19 3655.68,1878.19 3708.62,1878.19 3761.56,1878.19 3814.5,1878.19 3867.43,1878.19 2877.35,1880 3016.83,1923.87 2969.31,1926.42 2929.54,1927.37 2882.01,1929.92 3458.41,1943.42 3516.84,1943.42 3575.27,1943.42 3633.71,1943.42 3692.14,1943.42 3750.57,1943.42 3809,1943.42 3867.43,1943.42 3396.28,1948.36 3015.75,1973.08 2931.41,1975.63 2968.22,1975.63 2883.88,1978.18 3396.28,2011 3011.55,2012.45 2964.03,2015 2928.44,2018.54 2880.91,2021.1 3458.41,2022.16 3516.84,2022.16 3575.27,2022.16 3633.71,2022.16 3692.14,2022.16 3750.57,2022.16 3809,2022.16 3867.43,2022.16 3458.41,2100.9 3516.84,2100.9 3575.27,2100.9 3633.71,2100.9 3692.14,2100.9 3750.57,2100.9 3809,2100.9 3867.43,2100.9 3377,2133.01 3692.55,2173.74 3543.77,2176.3 3633.3,2177.09 3731,2176.3 3777.91,2176.3 3867.43,2177.09 3585.77,2179.64 3819.91,2179.64 3442.04,2186.81 3385.83,2192 3396.28,2240 3668,2242.98 3458.41,2244.09 3779.53,2244.86 3830.12,2244.46 3622.05,2246.78 3723,2246.78 2979,2258 3024.11,2258 3083.06,2257.73 3396.28,2326.01 3454.71,2326.01 3513.14,2326.01 3571.57,2326.01 3630,2326.01 3688.43,2326.01 3746.87,2326.01 3337.84,2404.75 3396.28,2404.75 3454.71,2404.75 3513.14,2404.75 3571.57,2404.75 3630,2404.75 3688.43,2404.75 3746.87,2404.75 3337.84,2462.56 3396.28,2462.56 3454.71,2462.56 3513.14,2462.56 3571.57,2462.56 3630,2462.56 3688.43,2462.56 3746.87,2462.56 3337.84,2541.3 3396.28,2541.3 3454.71,2541.3 3513.14,2541.3 3571.57,2541.3 3630,2541.3 3688.43,2541.3 3746.87,2541.3
  other v2: 3712,1022 3742,1022.34 2122,1346 2142.59,1412.92
  other v3: 824,509 874,509 113,655 112.19,833 760.47,835.47 532.54,883 761,885 313,1228.3 592.83,1595 547,1630.9 107.06,2068 538,2076 107,2126
ID_SCL: IC2.1 R102.1 TP10.1 U6.C17 | length 2231.1
  Top Layer LF-signals w5: 1889,1098.3 1918.95,1098.3 U6.C17@1934.7,1114.05 ; TP10.1@2659,123 2666.63,115.37 v2(2697.63,115.37) ; IC2.1@2712.73,168.09 2712.73,128.63 R102.1@2726,115.37
  Top Layer LF-signals w6: v2(1795,986) 1815.59,1006.59 1815.59,1027.15 1886.73,1098.3 1889,1098.3
  Top Layer LF-signals w6.89: v2(2697.63,115.37) R102.1@2726,115.37
  Mid-1 w6: v2(1691,178.67) 1680,189.67 1680,431.21 1770.09,521.31 1770.09,871.12 1795,896.02 v2(1795,986)
  Mid-2 w6.89: v2(1691,178.67) 1697.74,185.41 2627.59,185.41 v2(2697.63,115.37)
ID_SDA: IC2.3 R101.1 TP11.1 U6.E18 | length 2523.3
  Top Layer LF-signals w5: R101.1@2787.54,116.53 IC2.3@2787.54,168.09 ; v2(2809,168) 2825,152 TP11.1@2851,152
  Top Layer LF-signals w6: v2@1767.04,1177.04 U6.E18@1903.2,1177.04
  Top Layer LF-signals w6.89: IC2.3@2787.54,168.09 2808.91,168.09 v2(2809,168) v2@2809,169.65
  Mid-1 w6: v2(1653,233.54) 1607.46,233.54 1585,256 1585,421 1748.91,584.91 1748.91,912.13 1771,934.22 1771,965.02 1763.09,972.92 1763.09,1172.1 v2(1768,1177)
  Mid-2 w6.89: v2(1653,233.54) 1666.46,233.54 1701.8,198.21 2663.8,198.21 2694,168 v2(2809,168)
IFCLK: R019.2 U6.P17 | length 1377.6
  Top Layer LF-signals w5: 1885,1476.25 1918.95,1476.25 U6.P17@1934.7,1460.5
  Top Layer LF-signals w6: v2(887,1031) 887.91,1031.91 R019.2@906.65,1031.91 ; v2@1746.58,1441.93 1746.58,1447.75 1790.95,1492.12 1847.42,1492.12 1863.29,1476.25 1885,1476.25
  Mid-2 w6: v2(887,1031) 889,1033 889,1107 1126.09,1344.1 1126.09,1376.59 1137.51,1388 1494.69,1388 1544.41,1338.28 1612.77,1338.28 1712.49,1438 v2(1747,1438)
INT4: U6.D10 U10.22 | length 1478.6
  Top Layer LF-signals w5: U6.D10@2155.17,1145.54 2170.92,1129.8 2170.92,1019.17
  Top Layer LF-signals w6: U10.22@1000.8,1137.66 1041.66,1137.66 v2(1043,1139) ; v2(2170.92,931.92) 2170.92,1019.17
  Mid-2 w6: v2(1043,1139) 1042,1139 1227,954 1671.84,954 1693.92,931.92 v2(2170.92,931.92)
INT5#: U6.U12 U10.84 | length 851.6
  Top Layer LF-signals w5: 2076.43,1602 2076.43,1570.74 U6.U12@2092.18,1554.99
  Top Layer LF-signals w6: U10.84@1467.34,1722.31 1467.34,1765.34 v2(1475,1773) ; 2076.43,1602 2074.09,1604.34 2074.09,1683.1 v2(2087,1696)
  Signal Layer 1 w6: v2(1475,1773) 1503.72,1744.28 1787.71,1744.28 1829,1703 2080,1703 v2(2087,1696)
IRQ: IC7.40 U6.D18 | length 1843.6
  Top Layer LF-signals w5: 1871.31,1145.54 U6.D18@1903.2,1145.54
  Top Layer LF-signals w6: v2(1855,1146) 1902.74,1146 U6.D18@1903.2,1145.54 ; IC7.40@2898.03,514.2 v2(2898.81,493.03)
  Mid-1 w6: v2(1846,471) 1846,484 1856.81,494.81 1856.81,1144.19 v2(1855,1146)
  Mid-2 w6: v2(1846,471) 1868.03,493.03 v2(2898.81,493.03)
LED_POWER: Q1.5 R5.1 TP12.1 U6.J17 | length 2354.9
  Top Layer LF-signals w5: 1894,1287.28 1918.95,1287.28 U6.J17@1934.7,1303.02 ; TP12.1@2904,365 2909.72,359.28 R5.1@2909.72,294.59 Q1.5@2955.49,294.59
  Top Layer LF-signals w6: v2(1867,1297) 1876.73,1287.28 1894,1287.28
  Top Layer LF-signals w6.89: v2(2873.44,365) TP12.1@2904,365
  Mid-1 w6: v2(1867,1297) 1900.91,1263.1 1900.91,516.1 1887.07,502.26 1887.07,241.44 v2(1892.51,236)
  Mid-2 w6.89: v2(1892.51,236) 1979.69,236 1991.9,223.8 2720.8,223.8 2862,365 v2(2873.44,365)
LED_TXRX: Q1.2 R1.1 TP13.1 U6.F18 | length 2605.7
  Top Layer LF-signals w5: Q1.2@3049.98,294.59 3062.41,294.59 3120,237 3097,214 R1.1@3097,191.35
  Top Layer LF-signals w6: v2(1811,1205) 1832.08,1205 1836.99,1209.91 1861.59,1209.91 1862.96,1208.54 U6.F18@1903.2,1208.54
  Top Layer LF-signals w6.89: v2(3125,211) TP13.1@3125,237
  Mid-1 w6: v2(1782,233.54) 1782,866.19 1811,895.19 v2(1811,1205)
  Mid-2 w6.89: v2(1782,233.54) 1804.54,211 v2(3125,211)
M0: U6.P12 U8.19 | length 1971.9
  Top Layer LF-signals w6: v2@2078,1470 2087.5,1460.5 U6.P12@2092.18,1460.5
  Mid-1 w6: v2(1227,1879.42) 1227.34,1879.08 1227.34,1767.32 1213.09,1753.08 1213.09,1475.07 1231.76,1456.41 v2(1231.76,1283.96) ; v2(2064,1877) 2065,1876 2065,1645.94 2076.8,1634.14 2076.09,1633.44 2076.09,1519.4 2085.91,1509.59 2085.91,1496.41 2080,1490.51 v2(2080,1470) v2@2080,1467.73
  Mid-2 w6: v2(1227,1879.42) 1237.23,1869.19 1295.52,1869.19 1305.24,1878.91 2062.09,1878.91 v2(2064,1877)
  Bottom Layer LF-signals w6: v2(1231.76,1283.96) 1237.96,1277.76 U8.19@1306.35,1277.76
M1: U6.P13 U8.23 | length 2152.7
  Top Layer LF-signals w6: v2(2046,1449) 2057.5,1460.5 U6.P13@2060.68,1460.5
  Mid-1 w6: v2(1131,1928) 1093.17,1890.17 1093.17,1661.48 1168,1586.65 v2(1168,1347) ; v2(1980,1928) 1995,1913 1995,1614.8 2010.81,1598.99 2010.81,1498.09 2025.81,1483.09 2025.81,1455.68 2032.49,1449 v2(2046,1449)
  Mid-2 w6: v2(1131,1928) v2(1980,1928)
  Bottom Layer LF-signals w6: v2(1168,1347) 1177.56,1356.56 U8.23@1306.35,1356.56
M2: U6.P11 U8.24 | length 1835.5
  Top Layer LF-signals w6: U6.P11@2123.67,1460.5 2126.23,1460.5 v2(2142,1444.73)
  Mid-1 w6: v2(1258,1808) 1258,1781.15 1225,1748.15 1225,1480 1298,1407 v2(1299,1407) ; v2(2142,1444.73) 2142,1459.51 2153.91,1471.41 2153.91,1510.1 2153.75,1510.25 2170.92,1527.41 2170.92,1605.59 2153.91,1622.6 2153.91,1714.91 2168.16,1729.16 2168.16,1830.85 v2(2168,1831)
  Mid-2 w6: v2(1258,1808) 1278.09,1828.1 2165.09,1828.1 v2(2168,1831)
  Bottom Layer LF-signals w6: v2(1299,1407) 1306.35,1399.65 U8.24@1306.35,1376.26
MISO: IC7.44 U6.G17 | length 2160.5
  Top Layer LF-signals w5: v2(1843,1237) 1856.41,1223.6 1891.09,1223.6 1891.32,1223.83 1918.5,1223.83 U6.G17@1934.7,1240.03
  Top Layer LF-signals w6: v2(2972,446) 2976.77,450.77 IC7.44@2976.77,514.2
  Mid-1 w6: v2(1843,1237) 1838.97,1232.97 1838.97,920.52 1844.91,914.59 1844.91,778.88 1800.18,734.16 1800.18,481.79 1856.97,425 v2(1869,425)
  Mid-2 w6: v2(1869,425) 1878.41,434.41 2430.59,434.41 2435.81,429.19 2955.19,429.19 v2(2972,446)
MOSI: IC7.43 U6.H17 | length 2036.7
  Top Layer LF-signals w5: 1877.78,1255.78 1918.95,1255.78 U6.H17@1934.7,1271.53
  Top Layer LF-signals w6: v2(1863,1241) 1877.78,1255.78 ; v2(2957.09,469) IC7.43@2957.09,514.2
  Mid-1 w6: v2(1863,1241) 1863,1237.51 1871.09,1229.41 1871.09,828.59 1869.09,826.59 1869.09,451.03 v2(1865.07,447) v2(1865.07,447)
  Mid-2 w6: v2@1865.07,446.32 2874.87,446.32 2880.09,441.1 2931.67,441.1 2957.09,466.51 v2(2957.09,469)
MR#: U11.3
NetB1_1: B1.1 C3.1 | length 37
  Top Layer LF-signals w7: B1.1@3318.7,639.66 3323.47,639.66 cw(c3323.47,598.58) C3.1@3352.52,627.63
NetB1A_1: B1A.1 C3A.1 | length 54.4
  Top Layer LF-signals w7: B1A.1@3326.59,1929.53 3341.3,1929.53 cw(c3341.3,1879.04) C3A.1@3377,1914.74
NetC01_1: C01.1 U10.11 XL1.1 | length 204.7
  Top Layer LF-signals w7: C01.1@906.87,1344.86 XL1.1@906.87,1399.44 ; C01.1@915.73,1336 934.16,1336 946,1347.84 946,1400 965.16,1419.16 U10.11@1000.8,1419.16
NetC002_1: C002.1 U10.10 XL1.3 | length 271.9
  Top Layer LF-signals w7: XL1.3@836.01,1489.99 891.34,1545.32 C002.1@891.34,1551.81 914.19,1551.81 947,1519 947,1462.1 964.35,1444.75 U10.10@1000.8,1444.75
NetC3_2: C3.2 C21.1 R4.1 | length 446.6
  Top Layer LF-signals w8.27: C3.2@3365.74,614.41 3650.57,329.57 ccw(c3661.22,340.22) C21.1@3661.22,325.17 ; C21.1@3668.65,325.17 R4.1@3700.65,325.17
NetC3A_2: C3A.2 C21A.1 R4A.1 | length 398.7
  Top Layer LF-signals w8.27: C3A.2@3406.23,1885.51 3662.74,1629 R4A.1@3698.65,1629
NetC4_1: C4.1 R4.2 R10.2 SMA2.1 | length 237.6
  Top Layer LF-signals w8.27: R4.2@3719.35,325.17 C4.1@3761,325.17 SMA2.1@3957,325.17
NetC4A_1: C4A.1 R4A.2 R10A.2 SMA3.1 | length 239.6
  Top Layer LF-signals w8.27: R4A.2@3717.41,1628.95 C4A.1@3760,1628.95 SMA3.1@3957,1628.95
NetC5_1: C5.1 L1.3 | length 28.4
  Top Layer LF-signals w7: L1.3@3217,711.28 C5.1@3217,739.65
NetC5A_1: C5A.1 L1A.3 | length 28.5
  Top Layer LF-signals w7: L1A.3@3215.94,2006.53 3215.94,2035 C5A.1@3216,2035.05
NetC7_1: C7.1 R9.2 R11.2 SMA1.1 | length 222.6
  Top Layer LF-signals w8.37: R9.2@3734.35,977.06 SMA1.1@3957,977.06
NetC7A_1: C7A.1 R9A.2 R11A.2 SMA4.1 | length 221.5
  Top Layer LF-signals w8.27: R9A.2@3735.52,2280.84 SMA4.1@3957,2280.84
NetC8_1: C8.1 L1.2 | length 37.5
  Top Layer LF-signals w7: L1.2@3211.47,674.25 3247.9,674.25 C8.1@3248.65,675
NetC8_2: C8.2 C22.1 R9.1 | length 573.7
  Top Layer LF-signals w7.87: C8.2@3267.35,675 3569.41,977.06 cw(c3586.78,959.68) 3586.78,984.25 C22.1@3684.75,984.25 ; C22.1@3688,981 3691.95,977.06 R9.1@3715.65,977.06
NetC08A_1: C08A.1 L1A.2 | length 32.7
  Top Layer LF-signals w7: L1A.2@3215.94,1975.03 C08A.1@3248.65,1975.03
NetC08A_2: C08A.2 C22A.1 R9A.1 | length 570.6
  Top Layer LF-signals w8.27: C08A.2@3274,1972 3583,2281 R9A.1@3716.65,2281
NetC10_1: C10.1 C25.2 IC7.17@2976.77,787.82 R13.2 | length 107.3
  Top Layer LF-signals w6.89: R13.2@2980.81,836 C10.1@2980.81,863.95 C25.2@2980.81,892
  Top Layer LF-signals w7: IC7.17@2976.77,787.82 R13.2@2976.77,839.1
NetC10A_1: C10A.1 C25A.2 IC7A.17@2975.77,2083.28 R13A.2 | length 101.3
  Top Layer LF-signals w6.89: IC7A.17@2975.77,2083.28 2975.77,2118.77 R13A.2@2982,2125 ; R13A.2@2981,2126 C25A.2@2981,2183
NetC024A_1: C024A.1 IC8.1 P1A.1 TP8.1 XC1.3 | length 407.2
  Top Layer LF-signals w7: XC1.3@2992.43,1335 3032.43,1375 3081.78,1375 ; 3095.61,1375 3081.78,1375 ; C024A.1@3241.85,1339.02 IC8.1@3138.22,1339.02 3138.22,1357.99 3121.21,1375 3081.78,1375 ; C024A.1@3247.84,1333.03 TP8.1@3300.99,1333.03 ; TP8.1@3306.9,1338.94 P1A.1@3355.13,1338.94
NetC25_1: C25.1 IC8.4 | length 922.4
  Top Layer LF-signals w6.89: C25.1@2999.51,892 v2(2999.51,907.81) ; v2@3087.03,1250.03 IC8.4@3087.03,1266.98
  Bottom Layer LF-signals w5: v2(2999.51,907.81) 3087,995.3 3359.3,995.3 3371,1007 3371,1106 3358,1119 3159.35,1119 3087,1191.35 v2(3087,1250)
NetC27_1: C27.1 R14.1 | length 57.9
  Bottom Layer LF-signals w20: R14.1@197.01,645 C27.1@197.01,702.89
NetC28_1: C28.1 U1.7 | length 98.1
  Bottom Layer LF-signals w20: 207,783 U1.7@305.15,783
NetC32_1: C32.1 R17.1 | length 70.9
  Bottom Layer LF-signals w20: C32.1@172,1898.4 172,1880.32 R17.1@209.32,1843
NetC33_1: C33.1 U3.7 | length 137.1
  Bottom Layer LF-signals w20: C33.1@174.99,1983.78 U3.7@312.07,1983.78
NetC41_2: C41.2 U5.8
NetC42_1: C42.1 U5.4 | length 112.7
  Bottom Layer LF-signals w20: C42.1@198,389.86 217.32,409.18 U5.4@302.68,409.18
NetC42_2: C42.2 L7.1 U5.2 U5.3 | length 105.5
  Bottom Layer LF-signals w20: L7.1@89,314.63 C42.2@194.49,314.63
NetC46_1: C46.1 U5.7 | length 121.1
  Bottom Layer LF-signals w20: U5.7@528.66,309.18 C46.1@649.72,309.18
NetC47_1: C47.1 U06.1 U06.3
NetCON2_2: CON2.2 U10.18 | length 915.4
  Top Layer LF-signals w6.5: CON2.2@166.24,1328.59 199.02,1328.59 206.07,1321.55 230.25,1321.55 v2(234,1325.3) ; v2(959.29,1242) 961.13,1242 963.1,1240.02 U10.18@1000.8,1240.02
  Bottom Layer LF-signals w6.5: v2(234,1325.3) 231.43,1325.3 218.75,1312.61 218.75,1299.98 227.73,1291 256.67,1291 260.47,1294.8 881.21,1294.8 934,1242 v2(959.29,1242)
NetCON2_3: CON2.3 U10.17 | length 860.2
  Top Layer LF-signals w6.5: CON2.3@166.24,1303 199.02,1303 206.07,1310.05 230.25,1310.05 v2(234,1306.3) ; v2(959.29,1261) 963.1,1264.81 963.1,1265.61 U10.17@1000.8,1265.61
  Bottom Layer LF-signals w6.5: v2(234,1306.3) 885.97,1306.3 931.26,1261 v2(959.29,1261)
NetD1_1: D1.1 R2.2 | length 102.8
  Top Layer LF-signals w5: R2.2@2887.08,263.1 2887.08,223.02 D1.1@2931.43,178.67
NetD1_2: D1.2 R1.2 | length 86.1
  Top Layer LF-signals w20: D1.2@3014.11,178.67 3021.83,170.94 R1.2@3097,170.94
NetD1A_1: D1A.1 R2A.2 | length 65
  Top Layer LF-signals w7: D1A.1@3122.04,2456.67 R2A.2@3168,2410.7
NetD2_1: D2.1 R3.2 | length 352.1
  Top Layer LF-signals w5: D2.1@3006.3,88.63 3059.63,88.63 3163.78,192.78 3163.78,250.18 R3.2@3097.22,316.74
NetD2A1_2: D2A1.2 R15B.1 | length 45.9
  Top Layer LF-signals w20: D2A1.2@1366.34,1862 R15B.1@1412.25,1862
NetD2A_1: D2A.1 R3A.2
NetIC7_1: IC7.1 J104.1 | length 225.7
  Top Layer LF-signals w7: IC7.1@3084.06,542.74 3221.13,405.67 cw(c3192.46,377) J104.1@3233,377
NetIC7_2: IC7.2 J104.2 | length 180.1
  Top Layer LF-signals w7: IC7.2@3084.06,562.43 3106.57,562.43 cw(c3106.57,463.43) 3176.57,533.43 J104.2@3233,477
NetIC7_11: IC7.11@3084.06,739.59 J105.1 | length 177.7
  Top Layer LF-signals w7: IC7.11@3084.06,739.59 ccw(c3084.06,798.82) 3125.94,756.94 3166.42,797.42 cw(c3233,730.85) J105.1@3233,825
NetIC7_12: IC7.12@3084.06,759.28 J105.2 | length 225.7
  Top Layer LF-signals w7: IC7.12@3084.06,759.28 3221.14,896.36 ccw(c3192.49,925) J105.2@3233,925
NetIC7_18: IC7.18 R7.1 | length 63.2
  Top Layer LF-signals w7: R7.1@2941,844.37 2941,825.9 2957.09,809.81 IC7.18@2957.09,787.82
NetIC7_22: IC7.22 R12.2 | length 56.1
  Top Layer LF-signals w7: R12.2@2869,840.05 2878.35,830.71 IC7.22@2878.35,787.82
NetIC7A_1: IC7A.1 J104A.1 | length 241.9
  Top Layer LF-signals w7: IC7A.1@3083.06,1838.21 3088.32,1838.21 cw(c3088.32,1745.32) 3154,1811 3156,1809 cw(c3086,1738.99) 3185,1738.99 ccw(c3226.02,1738.99) 3197.02,1709.98 J104A.1@3233,1674
NetIC7A_2: IC7A.2 J104A.2 | length 180.4
  Top Layer LF-signals w7: IC7A.2@3083.06,1857.89 3108.1,1857.89 cw(c3108.1,1758.89) 3178.11,1828.89 J104A.2@3233,1774
NetIC7A_11: IC7A.11@3083.06,2035.06 J105A.1 | length 192.2
  Top Layer LF-signals w7: IC7A.11@3083.06,2035.06 3127.06,2035.06 3217,2125 J105A.1@3238,2125
NetIC7A_12: IC7A.12@3083.06,2054.74 J105A.2 | length 255.3
  Top Layer LF-signals w7: IC7A.12@3083.06,2054.74 3118.74,2054.74 3193,2129 3193,2180 J105A.2@3238,2225
NetIC7A_18: IC7A.18 R7A.1 | length 61.2
  Top Layer LF-signals w6.89: R7A.1@2942,2138.65 2942,2129.54 2956.09,2115.45 IC7A.18@2956.09,2083.28
NetIC7A_22: IC7A.22 R12A.2 | length 57.8
  Top Layer LF-signals w7: R12A.2@2871.44,2137.48 2870,2136.04 2870,2108 2877.35,2100.65 IC7A.22@2877.35,2083.28
NetIC8_5: IC8.5 W1.1 | length 30.8
  Top Layer LF-signals w7: W1.1@3112.63,1236.13 IC8.5@3112.63,1266.98
NetL4_1: L4.1 U1.9
NetL5_1: L5.1 U3.9
NetL8_1: L8.1 U06.5
NetP1_1: P1.1 R144.2 | length 134.5
  Top Layer LF-signals w5: R144.2@1239.34,1978 1255,1993.66 P1.1@1255,2106
NetP1_2: P1.2 R145.2 | length 127.6
  Top Layer LF-signals w5: R145.2@1355,1978.44 P1.2@1355,2106
NetP1_3: P1.3 R146.2 | length 113.2
  Top Layer LF-signals w5: R146.2@1469.78,1978 P1.3@1469.78,2091.22
NetP1_4: P1.4 R147.2 | length 140.4
  Top Layer LF-signals w5: P1.4@1555,2106 1585,2076 R147.2@1585,1978
NetP4_1: P4.1 R032.1 U12.3 | length 157.1
  Top Layer LF-signals w12: P4.1@1814,796 1906.09,796 1911.55,801.45 U12.3@1968.83,801.45
NetPio_1: Pio.1 U6.D8 | length 2241.3
  Top Layer LF-signals w5: v2(2207,1157) 2209,1157 2218.16,1147.84 U6.D8@2218.16,1145.54
  Mid-1 w6: v2(1404,1071) 1443.97,1110.97 1443.97,1977.54 1505,2038.57 1505,2343.35 Pio.1@1458.95,2389.4
  Mid-2 w6: v2(1404,1071) 1404.09,1071.1 1692.59,1071.1 1723.59,1102.1 1922.75,1102.1 1942.65,1122 2121.51,1122 2127.41,1116.1 2168.09,1116.1 2207,1155 v2(2207,1157)
NetPio_2: Pio.2 U6.C7 | length 2269.3
  Top Layer LF-signals w5: U6.C7@2249.66,1114.05 v2(2259.53,1123.92)
  Mid-1 w6: v2(1344,1045) 1432.06,1133.06 1432.06,2028.63 1413.82,2046.88 1413.82,2078.9 1414,2079.08 1414,2244.46 Pio.2@1458.95,2289.4
  Mid-2 w6: v2(1344,1045) 1345.09,1046.1 1717.59,1046.1 1726.49,1055 1875.65,1055 1905.75,1085.1 2220.71,1085.1 v2(2259.53,1123.92)
NetPio_3: Pio.3 U6.C2 | length 2513.4
  Top Layer LF-signals w5: U6.C2@2407.14,1114.05 2422.89,1098.3 2481.7,1098.3 v2(2483,1097)
  Mid-1 w6: v2(2483,1097) 2517.91,1131.91 2517.91,1225.84 2588.91,1296.84 2588.91,2079.91 2597,2088 v2(2597,2165)
  Signal Layer 1 w6: Pio.3@1558.95,2389.4 1505,2335.46 1505,2240.46 1581.74,2163.72 2481.79,2163.72 2505.51,2140 2572,2140 v2(2597,2165)
NetPio_4: Pio.4 U6.H1 | length 1993
  Top Layer LF-signals w5: U6.H1@2438.63,1271.53 2470.52,1271.53
  Top Layer LF-signals w6: 2470.52,1271.53 v2(2480.47,1271.53)
  Mid-1 w6: v2(2480.47,1271.53) 2512,1303.06 2512,2156 v2(2501,2167)
  Signal Layer 1 w6: Pio.4@1558.95,2289.4 1558.95,2212.06 1595.38,2175.62 2492.38,2175.62 v2(2501,2167)
NetPio_5: Pio.5 U6.G1 | length 2077.3
  Top Layer LF-signals w5: U6.G1@2438.63,1240.03 v2(2470.52,1240.03)
  Mid-1 w6: v2(2470,2201.91) 2485.09,2186.81 2485.09,2160.41 2496,2149.51 2496,1317 2464.57,1285.57 2464.57,1245.99 v2(2470.52,1240.03)
  Signal Layer 1 w6: Pio.5@1658.95,2389.4 1608.69,2339.15 1608.69,2243.31 1664.47,2187.53 2415.02,2187.53 2429.4,2201.91 v2(2470,2201.91)
NetPio_6: Pio.6 U6.F1 | length 1817.1
  Top Layer LF-signals w5: U6.F1@2438.63,1208.54 v2(2470.52,1208.54)
  Mid-1 w6: v2(2458,2075) 2458,1552.03 2482,1528.03 2482,1329.91 2452.66,1300.57 2452.66,1226.4 v2(2470.52,1208.54)
  Mid-2 w6: Pio.6@1658.95,2289.4 1658.95,2286.95 1870.9,2075 v2(2458,2075)
NetPio_7: Pio.7 U6.E1 | length 1951.9
  Top Layer LF-signals w5: U6.E1@2438.63,1177.04 v2(2462,1177.04)
  Mid-1 w6: v2(2435,2054.74) 2435,1450.59 2434,1449.59 2434,1205.04 v2(2462,1177.04)
  Mid-2 w6: Pio.7@1758.95,2389.4 1810,2338.35 1810,2152.73 1869.73,2093 2475,2093 2487.4,2080.6 2487.4,2062.4 2479.74,2054.74 v2(2435,2054.74)
NetPio_8: Pio.8 U6.J3 | length 1903.9
  Top Layer LF-signals w6: v2(2362,1289.38) U6.J3@2375.64,1303.02
  Mid-1 w6: v2(2362,1289.38) 2362,1482.58 2376.44,1497.02 2376.44,1510.19 2373,1513.63 2373,1642 2384,1653 v2(2384,2054)
  Mid-2 w6: Pio.8@1758.95,2289.4 1714.61,2333.74 1621.74,2333.74 1605.22,2317.22 1605.22,2246.78 1680,2172 1757.06,2172 1865.97,2063.1 2374.91,2063.1 v2(2384,2054)
NetPio_9: Pio.9 U6.J2 | length 1920.4
  Top Layer LF-signals w5: U6.J2@2407.14,1303.02 2422.89,1287.28 2496.22,1287.28 2536.26,1327.31 2558.69,1327.31 v2(2560,1326)
  Mid-1 w6: v2(2481,2256) 2496,2256 2560,2192 v2(2560,1326)
  Mid-2 w6: Pio.9@1858.95,2389.4 1915.54,2446 2373.16,2446 2481,2338.16 v2(2481,2256)
NetPio_10: Pio.10 U6.D7 | length 1621.4
  Top Layer LF-signals w5: v2(2239,1158) 2239,1156.2 U6.D7@2249.66,1145.54
  Mid-1 w6: v2(2191,2122) 2136.34,2067.35 2136.34,1701.35 2142,1695.7 2142,1617.67 2159.01,1600.66 2159.01,1532.34 2122.09,1495.43 2122.09,1453.08 2097,1427.99 2097,1411 2120.51,1387.49 2120.51,1372.32 2129.9,1362.93 2165.08,1362.93 2178,1350 2178,1321.98 2159.01,1302.99 2159.01,1236.19 2237.2,1158 v2(2239,1158)
  Mid-2 w6: Pio.10@1858.95,2289.4 1858.95,2149.56 1890.51,2118 2187,2118 v2(2191,2122)
NetPio_11: Pio.11 U6.D4 | length 1566.9
  Top Layer LF-signals w5: U6.D4@2344.15,1145.54 2345.54,1145.54 v2(2355,1155)
  Mid-1 w6: Pio.11@1958.95,2389.4 1911,2341.46 1911,2258 2002,2167 2196.49,2167 2239.38,2124.12 2239.38,2029.12 2251.28,2017.21 2251.28,1273.88 2257.81,1267.35 2257.81,1252.19 v2(2355,1155)
NetPio_12: Pio.12 U6.F4 | length 1362.8
  Top Layer LF-signals w5: U6.F4@2344.15,1208.54 v2(2354.21,1218.6)
  Mid-1 w6: Pio.12@1958.95,2289.4 2058.35,2190 2239.12,2190 2275.09,2154.02 2275.09,1283.74 2291.93,1266.91 2305.59,1266.91 2353.89,1218.6 v2(2354.21,1218.6)
NetPio_13: Pio.13 U6.F3 | length 1393.5
  Top Layer LF-signals w5: U6.F3@2375.64,1208.54 v2(2389,1221.89)
  Mid-1 w6: Pio.13@2058.95,2389.4 2111.27,2337.08 2111.27,2257.73 2150,2219 2179,2219 2196.09,2201.91 2244.05,2201.91 2336,2109.95 2336,1884 2305.43,1853.43 2305.43,1485.57 2318,1473 2318,1310 2389,1239 v2(2389,1221.89)
NetPio_14: Pio.14 U6.E2 | length 1466.3
  Top Layer LF-signals w5: v2@2395,1187.8 2395.2,1187.8 v2(2396,1187) 2396,1186.8 2405.76,1177.04 U6.E2@2407.14,1177.04
  Mid-1 w6: v2(2396,1187) 2422.09,1213.1 2422.09,1383.07 2403,1402.16 2403,1454.87 2407,1458.87 2407,1517.21 2405,1519.21 v2(2405,2205)
  Signal Layer 1 w6: Pio.14@2058.95,2289.4 2058.95,2239.24 2093.19,2205 v2(2405,2205)
NetPio_15: Pio.15 U6.H2 | length 1545.6
  Top Layer LF-signals w5: U6.H2@2407.14,1271.53 2422.89,1255.78 2491.68,1255.78 2544.09,1308.2 v2(2544.09,1311.91)
  Mid-1 w6: Pio.15@2158.95,2389.4 2209.35,2339 2292,2339 2313.79,2317.21 2313.79,2253.46 2331.25,2236 2487,2236 2544.09,2178.91 v2(2544.09,1311.91)
NetPio_16: Pio.16 U6.G2 | length 1470.4
  Top Layer LF-signals w5: U6.G2@2407.14,1240.03 2422.89,1224.28 v2(2489.25,1224.28)
  Mid-1 w6: Pio.16@2158.95,2289.4 2159.6,2289.4 2226.28,2222.72 2483.44,2222.72 2524,2182.16 2524,1291.41 2489.25,1256.66 v2(2489.25,1224.28)
NetPio_17: Pio.17 U6.C1 | length 1559.6
  Top Layer LF-signals w5: U6.C1@2438.63,1114.05 v2(2470.52,1114.05)
  Mid-1 w6: Pio.17@2258.95,2389.4 2311.35,2337 2442,2337 2577,2202 2577,1301.77 2506,1230.77 2506,1149.52 v2(2470.52,1114.05)
NetPio_18: Pio.18 U6.G6 | length 1067
  Top Layer LF-signals w5: U6.G6@2281.15,1240.03 2281.15,1241.15 v2(2291,1251)
  Mid-1 w6: v2(2258.81,2147.81) v2@2259,2148 ; v2@2259.62,2148 2259.62,2025.71 2263.19,2022.14 2263.19,1278.81 v2(2291,1251)
  Mid-2 w6: v2(2258.81,2147.81) 2258.95,2147.95 Pio.18@2258.95,2289.4
NetPio_19: Pio.19@2358.95,2389.4 U6.F6 | length 1719.5
  Top Layer LF-signals w5: v2(2269,1197) 2269.62,1197 U6.F6@2281.15,1208.54
  Mid-1 w6: v2(2231,2015) 2239.38,2006.62 2239.38,1268.95 2245.91,1262.42 2245.91,1244.1 2269,1221 v2(2269,1197)
  Signal Layer 1 w6: v2(2231,2015) 2529,2015 2624.81,2110.81 2624.81,2203.19 2438.6,2389.4 Pio.19@2358.95,2389.4
NetPio_20: Pio.20 U6.G4 | length 1533.9
  Top Layer LF-signals w6: U6.G4@2344.15,1240.03 v2(2354.12,1250)
  Mid-1 w6: v2(2308,2032) 2308,1891.05 2287,1870.05 2287,1317.79 2301.61,1303.18 2303.49,1303.18 2354.12,1252.56 v2(2354.12,1250)
  Signal Layer 1 w6: v2(2308,2032) 2518,2032 2612.91,2126.91 2612.91,2186.1 2581.19,2217.81 2430.54,2217.81 Pio.20@2358.95,2289.4
NetQ1_3: Q1.3 R3.1 | length 54.9
  Top Layer LF-signals w12: Q1.3@3049.98,331.99 3060.98,343 3089.66,343 R3.1@3097.22,335.44
NetQ1_6: Q1.6 R2.1 | length 43.8
  Top Layer LF-signals w12: R2.1@2905.78,263.1 Q1.6@2949.58,263.1
NetQ10_3: Q10.3 R3A.1 | length 48.9
  Top Layer LF-signals w12: R3A.1@2970.6,2310.35 Q10.3@3019.45,2310.35
NetQ10_6: Q10.6 R2A.1 | length 47.2
  Top Layer LF-signals w7: Q10.6@3116.56,2387.77 R2A.1@3163.78,2387.77
NetR14_2: R14.2 U1.5 | length 113.3
  Bottom Layer LF-signals w7: U1.5@277.75,684.4 U1.5@306.55,684.4
  Bottom Layer LF-signals w20: R14.2@238.35,645 267.15,645 U1.5@306.55,684.4
NetR015_1: R015.1 R16.2 U1.4 | length 163.5
  Bottom Layer LF-signals w7: U1.4@532.54,684.4 U1.4@571.6,684.4 ; R16.2@621.35,628.01 643,628.01 R015.1@651,628.01
  Bottom Layer LF-signals w20: U1.4@571.6,684.4 586.6,684.4 R015.1@643,628.01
